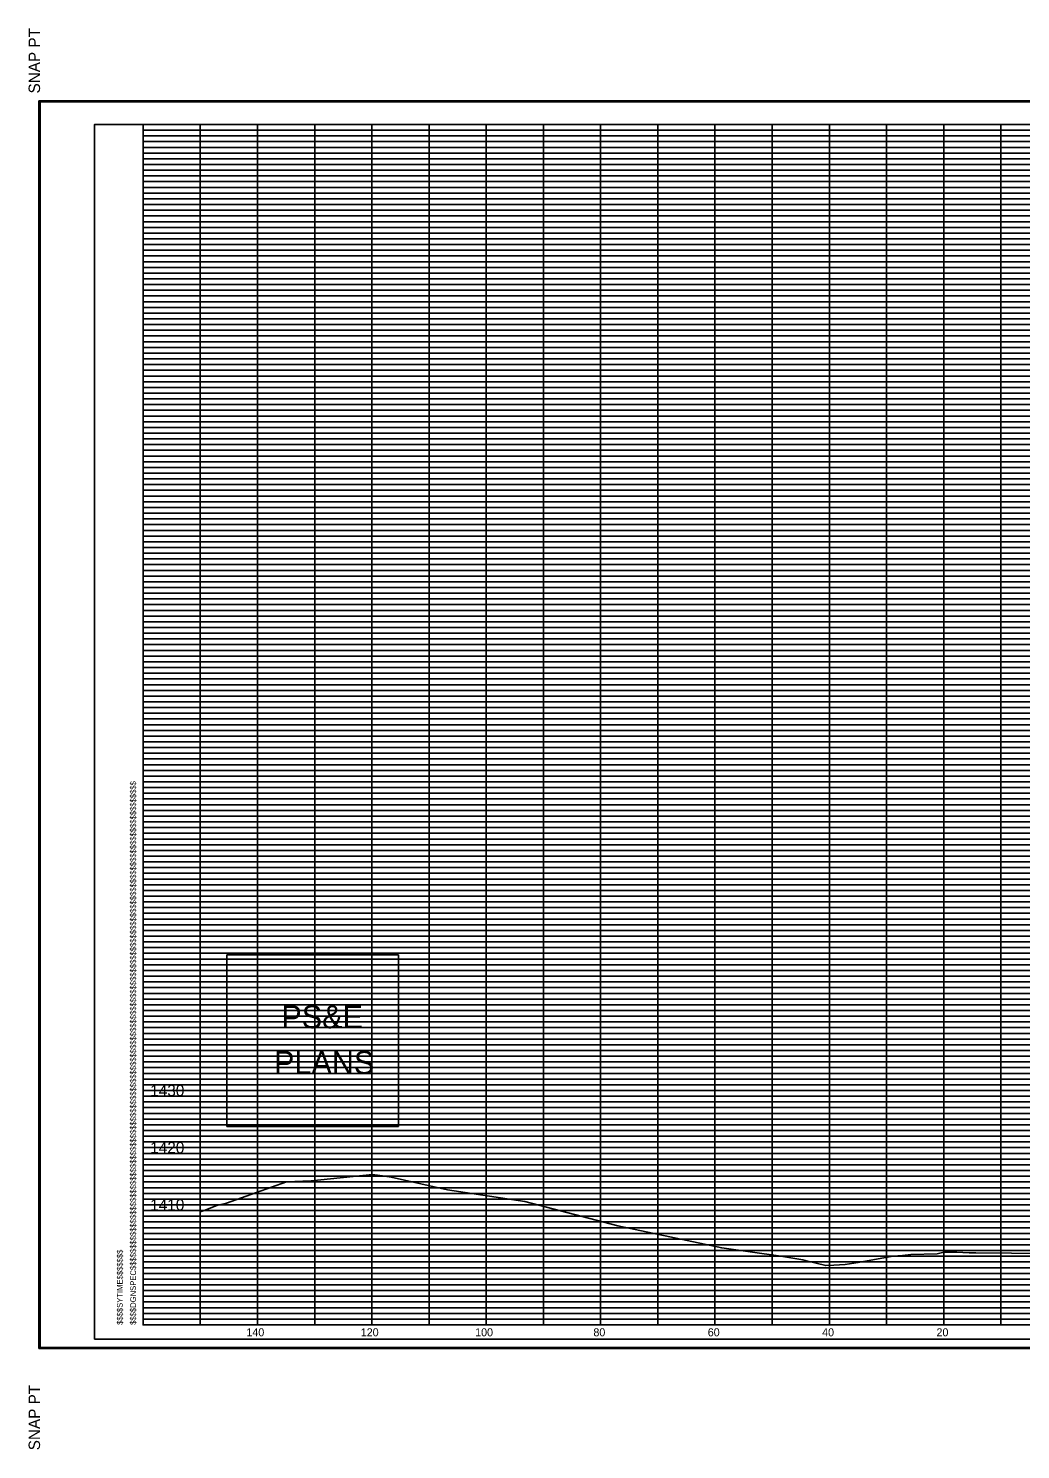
# Model space of a CAD drawing. Extents: x 980 to 1324, y 978 to 1497.
# Drawn here: x 979.9 to 1153.4, y 1248.2 to 1496.8 of the extents above; entities that cross this region are included whole.
import ezdxf

# ---------------------------------------------------------------- set-up
doc = ezdxf.new("R2010")
doc.units = 0
for name, color, linetype in [('DESIGN - SHEET - Corner Text', 7, 'Continuous'), ('DESIGN - SHEET - Light Grid', 7, 'Continuous'), ('DESIGN - SHEET - Linework', 7, 'Continuous'), ('DESIGN - SHEET - Plot Shape', 7, 'Continuous'), ('SURVEY - GROUND - Top of Ground', 7, 'Continuous')]:
    doc.layers.add(name, color=color, linetype=linetype)

# ---------------------------------------------------------------- blocks, each defined once
blk = doc.blocks.new('XSTSHT')
at = {"layer": 'DESIGN - SHEET - Light Grid'}
for p, q in [((0, 20.9), (8, 20.9)), ((8, 20.9), (16, 20.9)), ((0, 20.8), (8, 20.8)), ((0, 20.7), (8, 20.7)), ((8, 20.8), (16, 20.8)), ((8, 20.7), (16, 20.7)), ((0, 20.6), (8, 20.6)), ((0, 20.5), (8, 20.5)), ((0, 20.4), (8, 20.4)), ((8, 20.6), (16, 20.6)), ((8, 20.5), (16, 20.5)), ((8, 20.4), (16, 20.4)), ((0, 20.3), (8, 20.3)), ((0, 20.2), (8, 20.2)), ((8, 20.3), (16, 20.3)), ((8, 20.2), (16, 20.2)), ((0, 20.1), (8, 20.1)), ((0, 19.9), (8, 19.9)), ((8, 20.1), (16, 20.1)), ((8, 19.9), (16, 19.9)), ((0, 19.8), (8, 19.8)), ((0, 19.7), (8, 19.7)), ((8, 19.8), (16, 19.8)), ((8, 19.7), (16, 19.7)), ((0, 19.6), (8, 19.6)), ((0, 19.5), (8, 19.5)), ((0, 19.4), (8, 19.4)), ((8, 19.6), (16, 19.6)), ((8, 19.5), (16, 19.5)), ((8, 19.4), (16, 19.4)), ((0, 19.3), (8, 19.3)), ((0, 19.2), (8, 19.2)), ((8, 19.3), (16, 19.3)), ((8, 19.2), (16, 19.2)), ((0, 19.1), (8, 19.1)), ((0, 18.9), (8, 18.9)), ((8, 19.1), (16, 19.1)), ((8, 18.9), (16, 18.9)), ((0, 18.8), (8, 18.8)), ((0, 18.7), (8, 18.7)), ((8, 18.8), (16, 18.8)), ((8, 18.7), (16, 18.7)), ((0, 18.6), (8, 18.6)), ((0, 18.5), (8, 18.5)), ((0, 18.4), (8, 18.4)), ((8, 18.6), (16, 18.6)), ((8, 18.5), (16, 18.5)), ((8, 18.4), (16, 18.4)), ((0, 18.3), (8, 18.3)), ((0, 18.2), (8, 18.2)), ((8, 18.3), (16, 18.3)), ((8, 18.2), (16, 18.2)), ((0, 18.1), (8, 18.1)), ((8, 18.1), (16, 18.1)), ((0, 17.9), (8, 17.9)), ((0, 17.8), (8, 17.8)), ((0, 17.7), (8, 17.7)), ((8, 17.9), (16, 17.9)), ((8, 17.8), (16, 17.8)), ((8, 17.7), (16, 17.7)), ((0, 17.6), (8, 17.6)), ((0, 17.5), (8, 17.5)), ((8, 17.6), (16, 17.6)), ((8, 17.5), (16, 17.5)), ((0, 17.4), (8, 17.4)), ((0, 17.3), (8, 17.3)), ((0, 17.2), (8, 17.2)), ((8, 17.4), (16, 17.4)), ((8, 17.3), (16, 17.3)), ((8, 17.2), (16, 17.2)), ((0, 17.1), (8, 17.1)), ((8, 17.1), (16, 17.1)), ((0, 16.9), (8, 16.9)), ((0, 16.8), (8, 16.8)), ((0, 16.7), (8, 16.7)), ((8, 16.9), (16, 16.9)), ((8, 16.8), (16, 16.8)), ((8, 16.7), (16, 16.7)), ((0, 16.6), (8, 16.6)), ((0, 16.5), (8, 16.5)), ((8, 16.6), (16, 16.6)), ((8, 16.5), (16, 16.5)), ((0, 16.4), (8, 16.4)), ((0, 16.3), (8, 16.3)), ((0, 16.2), (8, 16.2)), ((8, 16.4), (16, 16.4)), ((8, 16.3), (16, 16.3)), ((8, 16.2), (16, 16.2)), ((0, 16.1), (8, 16.1)), ((8, 16.1), (16, 16.1)), ((0, 15.9), (8, 15.9)), ((0, 15.8), (8, 15.8)), ((0, 15.7), (8, 15.7)), ((8, 15.9), (16, 15.9)), ((8, 15.8), (16, 15.8)), ((8, 15.7), (16, 15.7)), ((0, 15.6), (8, 15.6)), ((0, 15.5), (8, 15.5)), ((8, 15.6), (16, 15.6)), ((8, 15.5), (16, 15.5)), ((0, 15.4), (8, 15.4)), ((0, 15.3), (8, 15.3)), ((0, 15.2), (8, 15.2)), ((8, 15.4), (16, 15.4)), ((8, 15.3), (16, 15.3)), ((8, 15.2), (16, 15.2)), ((0, 15.1), (8, 15.1)), ((8, 15.1), (16, 15.1)), ((0, 14.9), (8, 14.9)), ((0, 14.8), (8, 14.8)), ((0, 14.7), (8, 14.7)), ((8, 14.9), (16, 14.9)), ((8, 14.8), (16, 14.8)), ((8, 14.7), (16, 14.7)), ((0, 14.6), (8, 14.6)), ((0, 14.5), (8, 14.5)), ((8, 14.6), (16, 14.6)), ((8, 14.5), (16, 14.5)), ((0, 14.4), (8, 14.4)), ((0, 14.3), (8, 14.3)), ((0, 14.2), (8, 14.2)), ((8, 14.4), (16, 14.4)), ((8, 14.3), (16, 14.3)), ((8, 14.2), (16, 14.2)), ((0, 14.1), (8, 14.1)), ((8, 14.1), (16, 14.1)), ((0, 13.9), (8, 13.9)), ((0, 13.8), (8, 13.8)), ((0, 13.7), (8, 13.7)), ((8, 13.9), (16, 13.9)), ((8, 13.8), (16, 13.8)), ((8, 13.7), (16, 13.7)), ((0, 13.6), (8, 13.6)), ((0, 13.5), (8, 13.5)), ((8, 13.6), (16, 13.6)), ((8, 13.5), (16, 13.5)), ((0, 13.4), (8, 13.4)), ((0, 13.3), (8, 13.3)), ((0, 13.2), (8, 13.2)), ((8, 13.4), (16, 13.4)), ((8, 13.3), (16, 13.3)), ((8, 13.2), (16, 13.2)), ((0, 13.1), (8, 13.1)), ((8, 13.1), (16, 13.1)), ((0, 12.9), (8, 12.9)), ((0, 12.8), (8, 12.8)), ((0, 12.7), (8, 12.7)), ((8, 12.9), (16, 12.9)), ((8, 12.8), (16, 12.8)), ((8, 12.7), (16, 12.7)), ((0, 12.6), (8, 12.6)), ((0, 12.5), (8, 12.5)), ((8, 12.6), (16, 12.6)), ((8, 12.5), (16, 12.5)), ((0, 12.4), (8, 12.4)), ((0, 12.3), (8, 12.3)), ((0, 12.2), (8, 12.2)), ((8, 12.4), (16, 12.4)), ((8, 12.3), (16, 12.3)), ((8, 12.2), (16, 12.2)), ((0, 12.1), (8, 12.1)), ((8, 12.1), (16, 12.1)), ((0, 11.9), (8, 11.9)), ((0, 11.8), (8, 11.8)), ((0, 11.7), (8, 11.7)), ((8, 11.9), (16, 11.9)), ((8, 11.8), (16, 11.8)), ((8, 11.7), (16, 11.7)), ((0, 11.6), (8, 11.6)), ((0, 11.5), (8, 11.5)), ((8, 11.6), (16, 11.6)), ((8, 11.5), (16, 11.5)), ((0, 11.4), (8, 11.4)), ((0, 11.3), (8, 11.3)), ((0, 11.2), (8, 11.2)), ((8, 11.4), (16, 11.4)), ((8, 11.3), (16, 11.3)), ((8, 11.2), (16, 11.2)), ((0, 11.1), (8, 11.1)), ((8, 11.1), (16, 11.1)), ((0, 10.9), (8, 10.9)), ((0, 10.8), (8, 10.8)), ((0, 10.7), (8, 10.7)), ((8, 10.9), (16, 10.9)), ((8, 10.8), (16, 10.8)), ((8, 10.7), (16, 10.7)), ((0, 10.6), (8, 10.6)), ((0, 10.5), (8, 10.5)), ((8, 10.6), (16, 10.6)), ((8, 10.5), (16, 10.5)), ((0, 10.4), (8, 10.4)), ((0, 10.3), (8, 10.3)), ((0, 10.2), (8, 10.2)), ((8, 10.4), (16, 10.4)), ((8, 10.3), (16, 10.3)), ((8, 10.2), (16, 10.2)), ((0, 10.1), (8, 10.1)), ((8, 10.1), (16, 10.1)), ((0, 9.9), (8, 9.9)), ((0, 9.8), (8, 9.8)), ((0, 9.7), (8, 9.7)), ((8, 9.9), (16, 9.9)), ((8, 9.8), (16, 9.8)), ((8, 9.7), (16, 9.7)), ((0, 9.6), (8, 9.6)), ((0, 9.5), (8, 9.5)), ((8, 9.6), (16, 9.6)), ((8, 9.5), (16, 9.5)), ((0, 9.4), (8, 9.4)), ((0, 9.3), (8, 9.3)), ((0, 9.2), (8, 9.2)), ((8, 9.4), (16, 9.4)), ((8, 9.3), (16, 9.3)), ((8, 9.2), (16, 9.2)), ((0, 9.1), (8, 9.1)), ((8, 9.1), (16, 9.1)), ((0, 8.9), (8, 8.9)), ((0, 8.8), (8, 8.8)), ((8, 8.9), (16, 8.9)), ((8, 8.8), (16, 8.8)), ((0, 8.7), (8, 8.7)), ((0, 8.6), (8, 8.6)), ((0, 8.5), (8, 8.5)), ((8, 8.7), (16, 8.7)), ((8, 8.6), (16, 8.6)), ((8, 8.5), (16, 8.5)), ((0, 8.4), (8, 8.4)), ((0, 8.3), (8, 8.3)), ((8, 8.4), (16, 8.4)), ((8, 8.3), (16, 8.3)), ((0, 8.2), (8, 8.2)), ((0, 8.1), (8, 8.1)), ((8, 8.2), (16, 8.2)), ((8, 8.1), (16, 8.1)), ((0, 7.9), (8, 7.9)), ((0, 7.8), (8, 7.8)), ((8, 7.9), (16, 7.9)), ((8, 7.8), (16, 7.8)), ((0, 7.7), (8, 7.7)), ((0, 7.6), (8, 7.6)), ((0, 7.5), (8, 7.5)), ((8, 7.7), (16, 7.7)), ((8, 7.6), (16, 7.6)), ((8, 7.5), (16, 7.5)), ((0, 7.4), (8, 7.4)), ((0, 7.3), (8, 7.3)), ((8, 7.4), (16, 7.4)), ((8, 7.3), (16, 7.3)), ((0, 7.2), (8, 7.2)), ((0, 7.1), (8, 7.1)), ((8, 7.2), (16, 7.2)), ((8, 7.1), (16, 7.1)), ((0, 6.9), (8, 6.9)), ((0, 6.8), (8, 6.8)), ((8, 6.9), (16, 6.9)), ((8, 6.8), (16, 6.8)), ((0, 6.7), (8, 6.7)), ((0, 6.6), (8, 6.6)), ((0, 6.5), (8, 6.5)), ((8, 6.7), (16, 6.7)), ((8, 6.6), (16, 6.6)), ((8, 6.5), (16, 6.5)), ((0, 6.4), (8, 6.4)), ((0, 6.3), (8, 6.3)), ((8, 6.4), (16, 6.4)), ((8, 6.3), (16, 6.3)), ((0, 6.2), (8, 6.2)), ((0, 6.1), (8, 6.1)), ((8, 6.2), (16, 6.2)), ((8, 6.1), (16, 6.1)), ((0, 5.9), (8, 5.9)), ((0, 5.8), (8, 5.8)), ((8, 5.9), (16, 5.9)), ((8, 5.8), (16, 5.8)), ((0, 5.7), (8, 5.7)), ((0, 5.6), (8, 5.6)), ((0, 5.5), (8, 5.5)), ((8, 5.7), (16, 5.7)), ((8, 5.6), (16, 5.6)), ((8, 5.5), (16, 5.5)), ((0, 5.4), (8, 5.4)), ((0, 5.3), (8, 5.3)), ((8, 5.4), (16, 5.4)), ((8, 5.3), (16, 5.3)), ((0, 5.2), (8, 5.2)), ((0, 5.1), (8, 5.1)), ((8, 5.2), (16, 5.2)), ((8, 5.1), (16, 5.1)), ((0, 4.9), (8, 4.9)), ((0, 4.8), (8, 4.8)), ((8, 4.9), (16, 4.9)), ((8, 4.8), (16, 4.8)), ((0, 4.7), (8, 4.7)), ((0, 4.6), (8, 4.6)), ((0, 4.5), (8, 4.5)), ((8, 4.7), (16, 4.7)), ((8, 4.6), (16, 4.6)), ((8, 4.5), (16, 4.5)), ((0, 4.4), (8, 4.4)), ((0, 4.3), (8, 4.3)), ((8, 4.4), (16, 4.4)), ((8, 4.3), (16, 4.3)), ((0, 4.2), (8, 4.2)), ((0, 4.1), (8, 4.1)), ((8, 4.2), (16, 4.2)), ((8, 4.1), (16, 4.1)), ((0, 3.9), (8, 3.9)), ((0, 3.8), (8, 3.8)), ((8, 3.9), (16, 3.9)), ((8, 3.8), (16, 3.8)), ((0, 3.7), (8, 3.7)), ((0, 3.6), (8, 3.6)), ((0, 3.5), (8, 3.5)), ((8, 3.7), (16, 3.7)), ((8, 3.6), (16, 3.6)), ((8, 3.5), (16, 3.5)), ((0, 3.4), (8, 3.4)), ((0, 3.3), (8, 3.3)), ((8, 3.4), (16, 3.4)), ((8, 3.3), (16, 3.3)), ((0, 3.2), (8, 3.2)), ((0, 3.1), (8, 3.1)), ((8, 3.2), (16, 3.2)), ((8, 3.1), (16, 3.1)), ((0, 2.9), (8, 2.9)), ((0, 2.8), (8, 2.8)), ((8, 2.9), (16, 2.9)), ((8, 2.8), (16, 2.8)), ((0, 2.7), (8, 2.7)), ((0, 2.6), (8, 2.6)), ((0, 2.5), (8, 2.5)), ((8, 2.7), (16, 2.7)), ((8, 2.6), (16, 2.6)), ((8, 2.5), (16, 2.5)), ((0, 2.4), (8, 2.4)), ((0, 2.3), (8, 2.3)), ((8, 2.4), (16, 2.4)), ((8, 2.3), (16, 2.3)), ((0, 2.2), (8, 2.2)), ((0, 2.1), (8, 2.1)), ((8, 2.2), (16, 2.2)), ((8, 2.1), (16, 2.1)), ((0, 1.9), (8, 1.9)), ((0, 1.8), (8, 1.8)), ((8, 1.9), (16, 1.9)), ((8, 1.8), (16, 1.8)), ((0, 1.7), (8, 1.7)), ((0, 1.6), (8, 1.6)), ((0, 1.5), (8, 1.5)), ((8, 1.7), (16, 1.7)), ((8, 1.6), (16, 1.6)), ((8, 1.5), (16, 1.5)), ((0, 1.4), (8, 1.4)), ((0, 1.3), (8, 1.3)), ((8, 1.4), (16, 1.4)), ((8, 1.3), (16, 1.3)), ((0, 1.2), (8, 1.2)), ((0, 1.1), (8, 1.1)), ((8, 1.2), (16, 1.2)), ((8, 1.1), (16, 1.1)), ((0, 0.9), (8, 0.9)), ((0, 0.8), (8, 0.8)), ((8, 0.9), (16, 0.9)), ((8, 0.8), (16, 0.8)), ((0, 0.7), (8, 0.7)), ((0, 0.6), (8, 0.6)), ((0, 0.5), (8, 0.5)), ((8, 0.7), (16, 0.7)), ((8, 0.6), (16, 0.6)), ((8, 0.5), (16, 0.5)), ((0, 0.4), (8, 0.4)), ((0, 0.3), (8, 0.3)), ((8, 0.4), (16, 0.4)), ((8, 0.3), (16, 0.3)), ((0, 0.2), (8, 0.2)), ((0, 0.1), (8, 0.1)), ((8, 0.2), (16, 0.2)), ((8, 0.1), (16, 0.1))]:
    blk.add_line(p, q, dxfattribs=at)
at = {"layer": 'DESIGN - SHEET - Linework'}
for p, q in [((-1.823, -0.414), (-1.823, 21.414)), ((-1.823, 21.414), (32.217, 21.414)), ((1, 0), (1, 21)), ((2, 0), (2, 21)), ((3, 0), (3, 21)), ((4, 0), (4, 21)), ((5, 0), (5, 21)), ((6, 0), (6, 21)), ((7, 0), (7, 21)), ((8, 0), (8, 21)), ((9, 0), (9, 21)), ((10, 0), (10, 21)), ((11, 0), (11, 21)), ((12, 0), (12, 21)), ((13, 0), (13, 21)), ((14, 0), (14, 21)), ((15, 0), (15, 21)), ((0, 20), (28, 20)), ((0, 19), (32, 19)), ((0, 18), (32, 18)), ((0, 17), (32, 17)), ((0, 16), (32, 16)), ((0, 15), (32, 15)), ((0, 14), (32, 14)), ((0, 13), (32, 13)), ((0, 12), (32, 12)), ((0, 11), (32, 11)), ((0, 10), (32, 10)), ((0, 9), (32, 9)), ((0, 8), (32, 8)), ((0, 7), (32, 7)), ((0, 6), (32, 6)), ((0, 5), (32, 5)), ((0, 4), (32, 4)), ((0, 3), (32, 3)), ((0, 2), (32, 2)), ((0, 1), (32, 1)), ((-1.823, -0.414), (32.217, -0.414))]:
    blk.add_line(p, q, dxfattribs=at)
blk.add_lwpolyline([(0, 21), (0, 0), (32, 0), (32, 21), (0, 21)], dxfattribs=at)
at = {"layer": 'DESIGN - SHEET - Plot Shape'}
for points in [[(-1.803, 21.394), (32.197, 21.394), (32.197, -0.394), (-1.803, -0.394)], [(-0.85, 21), (32, 21), (32, -0.25), (-0.85, -0.25)]]:
    blk.add_lwpolyline(points, close=True, dxfattribs=at)
at = {"layer": 'DESIGN - SHEET - Corner Text'}
for s, height, p in [('  SNAP PT', 0.2, (-1.803, 21.394)), ('$$$$DGNSPEC$$$$$$$$$$$$$$$$$$$$$$$$$$$$$$$$$$$$$$$$$$$$$$$$$$$$$$$$$$$$$$$$$$$$$$$$$$$$$$$$$$$$$$$$$$$$$$$$$$$$$$$$$$$$$$$$$$$', 0.100002, (-0.126, 0)), ('$$$$SYTIME$$$$$$$', 0.1, (-0.358, 0)), ('SNAP PT  ', 0.2, (-1.803, -2.194))]:
    blk.add_text(s, height=height, rotation=90, dxfattribs=at).set_placement(p)

msp = doc.modelspace()

# ---------------------------------------------------------------- linework, layer by layer
at = {"layer": 'DESIGN - SHEET - Corner Text'}
msp.add_lwpolyline([(1014.65, 1334.71), (1014.65, 1304.71), (1044.65, 1304.71), (1044.65, 1334.71)], close=True, dxfattribs=at)
at = {"layer": 'DESIGN - SHEET - Plot Shape'}
msp.add_lwpolyline([(991.5, 1267.5), (1320, 1267.5), (1320, 1480), (991.5, 1480)], close=True, dxfattribs=at)
at = {"layer": 'SURVEY - GROUND - Top of Ground'}
msp.add_lwpolyline([(1010, 1289.8), (1010.65, 1290.01), (1012.91, 1290.91), (1014.55, 1291.29), (1025.07, 1295), (1029.36, 1295.19), (1040.1, 1296.29), (1041.86, 1296.07), (1043.36, 1295.83), (1053.22, 1293.65), (1066.72, 1291.57), (1083.01, 1287.3), (1101.19, 1283.46), (1111.52, 1282), (1115.37, 1281.39), (1115.78, 1281.25), (1119.37, 1280.37), (1120.77, 1280.45), (1122.76, 1280.58), (1125.03, 1280.9), (1131.12, 1281.99), (1132.77, 1282.12), (1134.24, 1282.31), (1138.85, 1282.44), (1140.05, 1282.71), (1142.3, 1282.72), (1143.33, 1282.68), (1144.48, 1282.63), (1145.62, 1282.62), (1151.84, 1282.57), (1158.57, 1282.4)], dxfattribs=at)

# ---------------------------------------------------------------- block references
at = {"layer": 'DESIGN - SHEET - Corner Text', "xscale": 10, "yscale": 10}
msp.add_blockref('XSTSHT', (1000, 1270), dxfattribs=at)

# ---------------------------------------------------------------- texts
at = {"layer": 'DESIGN - SHEET - Corner Text'}
for s, height, p in [('PS&E', 4, (1024.17, 1321.89)), ('PLANS', 4, (1022.89, 1313.89)), ('1430', 2, (1001.25, 1310)), ('1420', 2, (1001.25, 1300)), ('1410', 2, (1001.25, 1290)), ('140', 1.4, (1018.06, 1268)), ('120', 1.4, (1038.06, 1268)), ('100', 1.4, (1058.06, 1268)), ('80', 1.4, (1078.74, 1268)), ('60', 1.4, (1098.74, 1268)), ('40', 1.4, (1118.74, 1268)), ('20', 1.4, (1138.74, 1268))]:
    msp.add_text(s, height=height, dxfattribs=at).set_placement(p)

doc.saveas('drawing.dxf')
